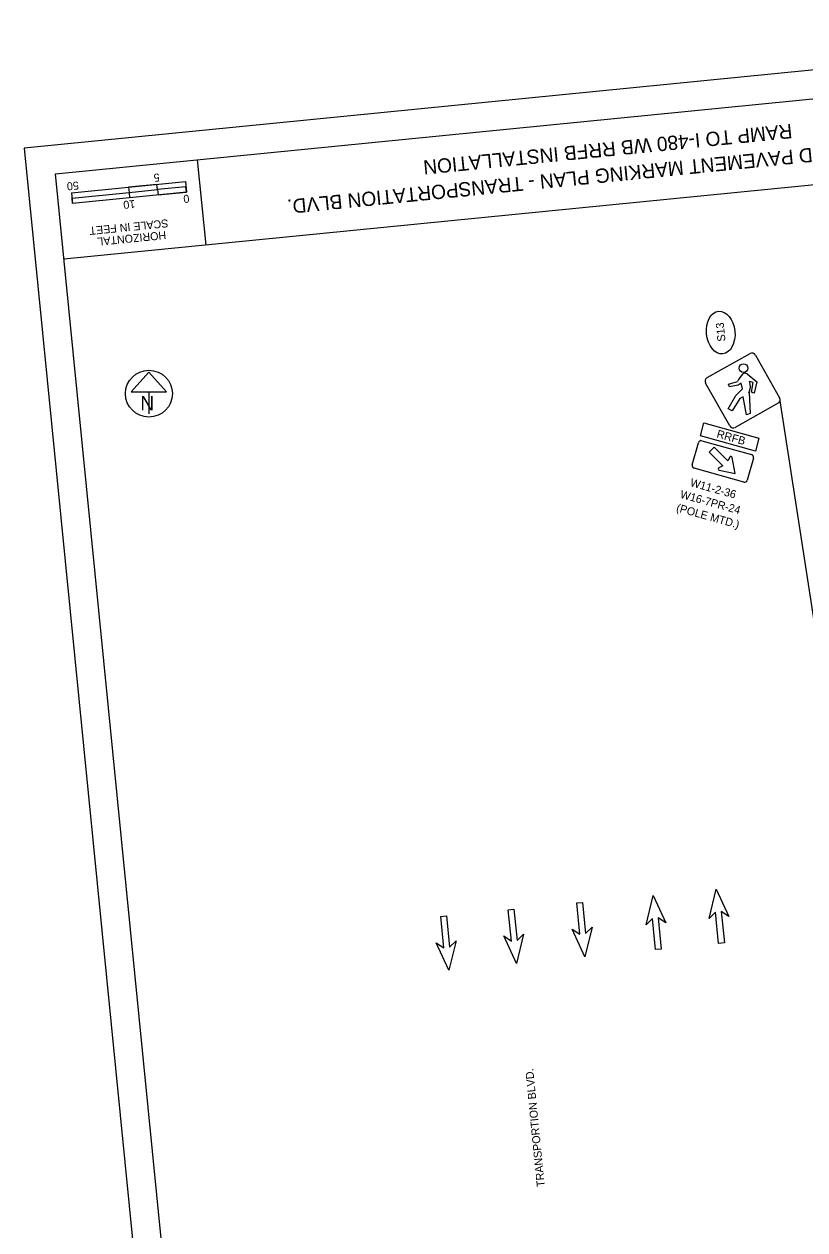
# Model space of a CAD drawing. Extents: x 2210919 to 2211172, y 637144 to 637504.
# Drawn here: x 2210919.3 to 2211055.9, y 637293.5 to 637504.5 of the extents above; entities that cross this region are included whole.
import ezdxf

# ---------------------------------------------------------------- set-up
doc = ezdxf.new("R2010")
doc.units = 0
for name, color, linetype in [('PM_P_Cells', 7, 'Continuous'), ('SH_Border', 7, 'Continuous'), ('SH_Cut_Line', 7, 'Continuous'), ('SH_Data', 7, 'Continuous'), ('SH_Masking', 7, 'Continuous'), ('SH_Text', 7, 'Continuous'), ('SN_P_Signs', 7, 'Continuous'), ('SN_P_Text', 7, 'Continuous')]:
    doc.layers.add(name, color=color, linetype=linetype)

msp = doc.modelspace()

# ---------------------------------------------------------------- linework, layer by layer
at = {"layer": 'PM_P_Cells'}
for p, q in [((2211028.08, 637346.88), (2211029.31, 637352.03)), ((2211029.31, 637352.03), (2211029.31, 637352.03)), ((2211029.31, 637352.03), (2211031.53, 637347.23)), ((2211039.11, 637347.98), (2211040.34, 637353.13)), ((2211040.34, 637353.13), (2211040.34, 637353.13)), ((2211040.34, 637353.13), (2211042.56, 637348.32)), ((2211015.96, 637350.71), (2211016.96, 637350.8)), ((2211016.51, 637345.23), (2211015.96, 637350.71)), ((2211016.46, 637350.76), (2211016.46, 637350.76)), ((2211016.96, 637350.8), (2211017.5, 637345.33)), ((2210992.18, 637348.35), (2210993.17, 637348.44)), ((2210992.72, 637342.87), (2210992.18, 637348.35)), ((2210992.67, 637348.4), (2210992.67, 637348.4)), ((2210993.17, 637348.44), (2210993.72, 637342.97)), ((2211003.99, 637349.52), (2211004.98, 637349.62)), ((2211004.53, 637344.04), (2211003.99, 637349.52)), ((2211004.49, 637349.57), (2211004.49, 637349.57)), ((2211004.98, 637349.62), (2211005.53, 637344.14)), ((2211029.21, 637348), (2211028.08, 637346.88)), ((2211029.75, 637342.53), (2211029.21, 637348)), ((2211031.53, 637347.23), (2211030.2, 637348.1)), ((2211030.2, 637348.1), (2211030.75, 637342.63)), ((2211040.24, 637349.1), (2211039.11, 637347.98)), ((2211040.78, 637343.62), (2211040.24, 637349.1)), ((2211042.56, 637348.32), (2211041.24, 637349.19)), ((2211041.24, 637349.19), (2211041.78, 637343.72)), ((2211017.4, 637341.3), (2211015.18, 637346.11)), ((2211015.18, 637346.11), (2211016.51, 637345.23)), ((2211018.63, 637346.45), (2211017.4, 637341.3)), ((2211017.5, 637345.33), (2211018.63, 637346.45)), ((2210993.61, 637338.94), (2210991.39, 637343.75)), ((2210991.39, 637343.75), (2210992.72, 637342.87)), ((2210994.85, 637344.09), (2210993.61, 637338.94)), ((2210993.72, 637342.97), (2210994.85, 637344.09)), ((2211005.42, 637340.11), (2211003.2, 637344.92)), ((2211003.2, 637344.92), (2211004.53, 637344.04)), ((2211006.66, 637345.26), (2211005.42, 637340.11)), ((2211005.53, 637344.14), (2211006.66, 637345.26)), ((2211041.78, 637343.72), (2211040.78, 637343.62)), ((2211041.28, 637343.67), (2211041.28, 637343.67)), ((2211030.75, 637342.63), (2211029.75, 637342.53)), ((2211030.25, 637342.58), (2211030.25, 637342.58)), ((2211005.42, 637340.11), (2211005.42, 637340.11)), ((2211017.4, 637341.3), (2211017.4, 637341.3)), ((2210993.61, 637338.94), (2210993.61, 637338.94))]:
    msp.add_line(p, q, dxfattribs=at)
at = {"layer": 'SH_Border'}
for p, q in [((2211135.22, 637484.05), (2210926.25, 637463.32)), ((2210951.13, 637465.79), (2210949.65, 637480.71))]:
    msp.add_line(p, q, dxfattribs=at)
msp.add_lwpolyline([(2210956.37, 637159.81), (2210924.77, 637478.24), (2211133.74, 637498.98), (2211165.34, 637180.55)], close=True, dxfattribs=at)
at = {"layer": 'SH_Cut_Line'}
msp.add_lwpolyline([(2211171.8, 637166.11), (2211138.22, 637504.45), (2210919.3, 637482.73), (2210952.88, 637144.39)], close=True, dxfattribs=at)
at = {"layer": 'SH_Data'}
for p, q in [((2210927.61, 637474.95), (2210947.51, 637476.93)), ((2210942.54, 637476.42), (2210937.56, 637475.93)), ((2210942.63, 637475.49), (2210942.54, 637476.42)), ((2210947.51, 637476.93), (2210947.7, 637475.06)), ((2210927.61, 637474.95), (2210927.79, 637473.08)), ((2210927.7, 637474.02), (2210937.65, 637475.01)), ((2210947.7, 637475.06), (2210927.79, 637473.08)), ((2210937.56, 637475.93), (2210937.65, 637475)), ((2210937.65, 637475), (2210942.63, 637475.49)), ((2210937.65, 637475.01), (2210937.74, 637474.07)), ((2210947.6, 637475.99), (2210942.63, 637475.49)), ((2210942.63, 637475.49), (2210942.72, 637474.57)), ((2210942.72, 637474.57), (2210947.7, 637475.06)), ((2210947.7, 637475.06), (2210947.6, 637475.99)), ((2210927.7, 637474.01), (2210927.7, 637474.02)), ((2210927.79, 637473.08), (2210927.7, 637474.01)), ((2210937.74, 637474.07), (2210927.79, 637473.08))]:
    msp.add_line(p, q, dxfattribs=at)
at = {"layer": 'SH_Masking'}
msp.add_circle((2210941.13, 637439.8), 4.1, dxfattribs=at)
at = {"layer": 'SH_Text'}
for p, q in [((2210941.13, 637443.54), (2210938.05, 637440.13)), ((2210944.21, 637440.13), (2210941.13, 637443.54)), ((2210938.05, 637440.13), (2210944.21, 637440.13)), ((2210941.13, 637440.13), (2210941.13, 637436.26)), ((2211051.51, 637438.53), (2211062.12, 637369.51)), ((2211040.02, 637430.44), (2211039.15, 637429.59)), ((2211042.37, 637428.03), (2211040.02, 637430.44)), ((2211039.15, 637429.59), (2211041.5, 637427.18)), ((2211042.72, 637428.69), (2211042.37, 637428.03)), ((2211041.5, 637427.18), (2211040.84, 637426.85)), ((2211040.9, 637426.4), (2211040.9, 637426.4))]:
    msp.add_line(p, q, dxfattribs=at)
msp.add_lwpolyline([(2211038.21, 637434.69), (2211047.84, 637432), (2211047.21, 637429.75), (2211037.58, 637432.44)], close=True, dxfattribs=at)
for points in [[(2211036.16, 637427.36), (2211037.24, 637431.21)], [(2211037.85, 637431.56), (2211046.52, 637429.14)], [(2211040.9, 637426.4), (2211043.66, 637425.84), (2211043.17, 637428.62)], [(2211046.87, 637428.52), (2211045.79, 637424.67)], [(2211045.17, 637424.32), (2211036.51, 637426.74)]]:
    msp.add_lwpolyline(points, dxfattribs=at)
msp.add_circle((2210941.13, 637439.8), 4.1, dxfattribs=at)
for centre, radius, start, end in [((2211037.72, 637431.08), 0.5, 74.3891, 164.3891), ((2211042.93, 637428.58), 0.243, 10.0654, 152.2019), ((2211046.38, 637428.66), 0.5, 344.3891, 74.3891), ((2211036.64, 637427.23), 0.5, 164.3891, 254.3891), ((2211040.95, 637426.63), 0.243, 116.5762, 258.7128), ((2211045.31, 637424.8), 0.5, 254.3891, 344.3891)]:
    msp.add_arc(centre, radius, start, end, dxfattribs=at)
msp.add_ellipse((2211041.14, 637450.49), major_axis=(-0.37, 3.73), ratio=0.666667, dxfattribs=at)
at = {"layer": 'SN_P_Signs'}
for p, q in [((2211045.79, 637443.27), (2211047.46, 637441.89)), ((2211042.51, 637441.47), (2211044.08, 637441.94)), ((2211042.68, 637440.97), (2211042.51, 637441.47)), ((2211044.21, 637441.3), (2211042.68, 637440.97)), ((2211043.8, 637439.45), (2211044.95, 637440.64)), ((2211044.71, 637441.61), (2211044.21, 637441.3)), ((2211044.95, 637440.64), (2211044.71, 637441.61)), ((2211046.81, 637441.78), (2211046.18, 637441.95)), ((2211046.53, 637440.04), (2211046.81, 637441.78)), ((2211047.46, 637441.89), (2211047.01, 637439.91)), ((2211042.43, 637437.12), (2211043.8, 637439.45)), ((2211044.48, 637438.96), (2211043.15, 637436.77)), ((2211045.08, 637439.24), (2211044.48, 637438.96)), ((2211045.63, 637436.08), (2211045.08, 637439.24)), ((2211046.11, 637440.01), (2211046.32, 637436.33)), ((2211047.01, 637439.91), (2211046.53, 637440.04)), ((2211043.15, 637436.77), (2211042.43, 637437.12)), ((2211046.32, 637436.33), (2211045.63, 637436.08))]:
    msp.add_line(p, q, dxfattribs=at)
for points in [[(2211038.78, 637442.6), (2211046.27, 637446.82)], [(2211047.23, 637446.55), (2211051.45, 637439.06)], [(2211042.73, 637434.15), (2211038.51, 637441.65)], [(2211051.18, 637438.11), (2211043.69, 637433.89)]]:
    msp.add_lwpolyline(points, dxfattribs=at)
msp.add_circle((2211045.14, 637444.28), 0.758, dxfattribs=at)
for centre, radius, start, end in [((2211046.62, 637446.21), 0.7, 29.3891, 119.3891), ((2211039.12, 637441.99), 0.7, 119.3891, 209.3891), ((2211048.45, 637439.84), 4.85, 135.9302, 154.4207), ((2211045.42, 637442.61), 0.751, 60.6332, 126.8841), ((2211043.51, 637441.06), 2.82, 336.2392, 18.45), ((2211050.84, 637438.72), 0.7, 299.3891, 29.3891), ((2211043.34, 637434.5), 0.7, 209.3891, 299.3891)]:
    msp.add_arc(centre, radius, start, end, dxfattribs=at)

# ---------------------------------------------------------------- texts
at = {"layer": 'SH_Data'}
for s, height, p in [('RAMP TO I-480 WB RRFB INSTALLATION', 2.5, (2211053.52, 637487)), ('SIGNING AND PAVEMENT MARKING PLAN - TRANSPORTATION BLVD.', 2.5, (2211076.68, 637484.78)), ('50', 1.4, (2210928.79, 637476.94)), ('5', 1.4, (2210942.94, 637478.34)), ('0', 1.4, (2210948.13, 637474.64)), ('10', 1.4, (2210938.66, 637473.7)), ('SCALE IN FEET', 1.4, (2210944.44, 637470.32)), ('HORIZONTAL', 1.4, (2210944.06, 637468.25))]:
    msp.add_text(s, height=height, rotation=185.6672, dxfattribs=at).set_placement(p)
at = {"layer": 'SH_Text'}
for s, height, rotation, p in [('S13', 1.4, 95.6672, (2211041.99, 637448.99)), ('N', 2.5, 360, (2210939.62, 637436.89)), ('TRANSPORTION BLVD.', 1.4, 95.6672, (2211010.39, 637301.09))]:
    msp.add_text(s, height=height, rotation=rotation, dxfattribs=at).set_placement(p)
at = {"layer": 'SN_P_Text'}
for s, p in [('RRFB', (2211040.33, 637432.16)), ('W11-2-36', (2211035.69, 637423.65)), ('W16-7PR-24', (2211033.95, 637421.6)), ('(POLE MTD.)', (2211033.27, 637419.24))]:
    msp.add_text(s, height=1.4, rotation=344.3891, dxfattribs=at).set_placement(p)

doc.saveas('drawing.dxf')
